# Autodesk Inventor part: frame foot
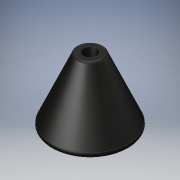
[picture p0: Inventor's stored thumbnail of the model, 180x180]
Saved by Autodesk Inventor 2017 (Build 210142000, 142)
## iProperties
Created: 2016-07
Part Number: frame foot
Material: Generic
Document SubType Name: Modeling
Designer: Stan
Density: 1 g/cm^3
Appearance: Glossy - Black
Author: Stan
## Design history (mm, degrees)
sketch "Sketch1"
  geometry: L1 (0, 0)-(0, -25.4); L2 (0, 0)-(-4.763, 0); L3 (-4.763, 0)-(-15.875, -25.4); L4 (-15.875, -25.4)-(0, -25.4)
  constraints: 8 end point, 1 horizontal, 1 parallel, 1 vertical
  dimensions: "d0" = 25.4 distance of L1.start L1.end; "d1" = 4.7625 distance of L1.start L2.end; "d2" = 15.875 distance of L3.end L1.end
revolve "Revolution1" sketch "Sketch1" stored, may be unused: angle "d3" = 90 deg
sketch "Sketch2"
  geometry: C1 r 2.54 at (0, 0); 1 further point
  constraints: 1 centre point, 1 coincident
  dimensions: "d4" = 5.08 diameter of C1
extrude "Extrusion1" cut sketch "Sketch2" distance "d5" = 25.4; taper "d6" = 0 deg
sketch "Sketch3"
  geometry: C1 r 7.938 at (0, 0); 1 further point
  constraints: 1 centre point, 1 coincident
  dimensions: "d7" = 15.875 diameter of C1
extrude "Extrusion2" cut sketch "Sketch3" distance "d8" = 12.7; taper "d9" = 0 deg
fillet "Fillet1" dims "d10" = 1.524
fillet "Fillet2" dims "d11" = 0.762
body "Solid1"
